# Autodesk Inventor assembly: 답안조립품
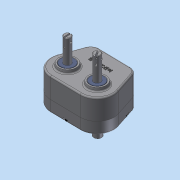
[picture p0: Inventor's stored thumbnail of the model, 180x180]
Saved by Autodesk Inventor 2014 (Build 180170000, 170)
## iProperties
Created: 2014-12
Part Number: 답안조립품
Document SubType Name: Assembly
Designer: user
Author: user
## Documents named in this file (14)
- C:\Users\user\Desktop\441208V1041\답안조립품.iam
- C:\Users\user\Desktop\441208V1041\답안본체.ipt
- C:\Users\user\Desktop\441208V1041\베어링- 6203.ipt
- C:\Users\user\Desktop\441208V1041\서브축.ipt
- C:\Users\user\Desktop\441208V1041\키5x5.ipt
- C:\Users\user\Desktop\441208V1041\서브기어.ipt
- C:\Users\user\Desktop\441208V1041\베어링- 6202.ipt
- C:\Users\user\Desktop\441208V1041\멈춤링.ipt
- C:\Users\user\Desktop\441208V1041\메인축.ipt
- C:\Users\user\Desktop\441208V1041\메인기어.ipt
- C:\Users\user\Desktop\441208V1041\커버.ipt
- C:\Users\user\Desktop\441208V1041\오일시일-D-17.ipt
- C:\Users\user\Desktop\441208V1041\오일시일-D-15.ipt
- C:\Users\user\Desktop\441208V1041\M 5 x 35.ipt
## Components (15 placed, 6 different names)
1. KS B 2023 6202 - 15 x 35 x 11:1
2. KS B 2023 6202 - 15 x 35 x 11:2
3. KS B 1336 17 x 1:1
4. KS B 1336 17 x 1:2
5. KS B 2023 6203 - 17 x 40 x 12:1
6. KS B 2023 6203 - 17 x 40 x 12:2
7. KS B 2023 6203 - 17 x 40 x 12:3
8. KS B 1336 17 x 1:3
9. KS B 2023 6203 - 17 x 40 x 12:4
10. KS B 2804 D D - 17 30 8:1
11. KS B 2804 D D - 15 30 7:1
12. KS B 2804 D D - 15 30 7:2
13. KS B 1003 - 미터 M 5 x 35:1 — 각도:5
14. KS B 1003 - 미터 M 5 x 35:2 — 각도:4
15. KS B 1003 - 미터 M 5 x 35:3 — 각도:6
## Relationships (3: Angle 3)
- 각도:4 [Angle]: KS B 1003 - 미터 M 5 x 35:2
- 각도:5 [Angle]: KS B 1003 - 미터 M 5 x 35:1
- 각도:6 [Angle]: KS B 1003 - 미터 M 5 x 35:3
